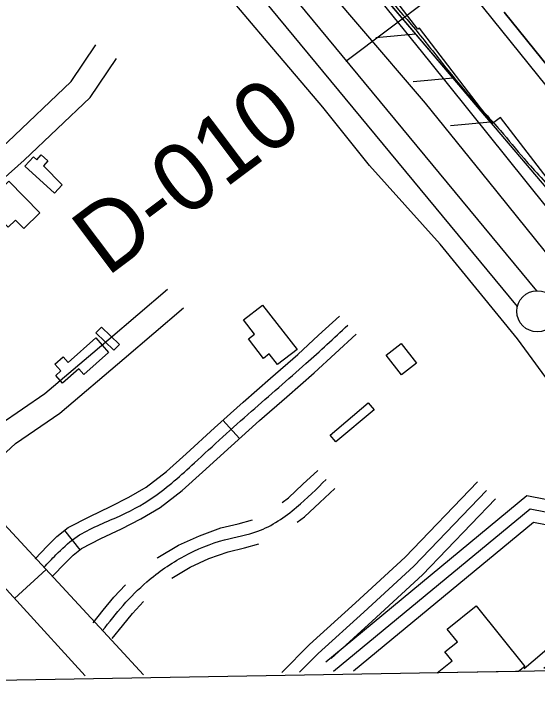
# Model space of a CAD drawing. Extents: x 3887375 to 3925618, y 296674 to 322633.
# Drawn here: x 3900685 to 3901319, y 302226 to 303069 of the extents above; entities that cross this region are included whole.
import ezdxf

# ---------------------------------------------------------------- set-up
doc = ezdxf.new("R2010")
doc.units = 0
for name, color, linetype in [('V-BLDG-OTLN', 7, 'Continuous'), ('V-GRID-FRAM', 7, 'Continuous'), ('V-LEVE-TOET', 7, 'Continuous'), ('V-RIVR-EDGE', 7, 'Continuous'), ('V-RIVR-RANG', 7, 'Continuous'), ('V-RIVR-RANG-IDEN', 7, 'Continuous'), ('V-ROAD-CNTR', 7, 'Continuous'), ('V-RRAP-FSHR', 7, 'Continuous'), ('V-RRAP-RVMT', 7, 'Continuous'), ('V-SURV-LINE', 7, 'Continuous'), ('V-TOPO-DPTH', 7, 'Continuous'), ('V-TOPO-MINR', 7, 'Continuous')]:
    doc.layers.add(name, color=color, linetype=linetype)

msp = doc.modelspace()

# ---------------------------------------------------------------- linework, layer by layer
at = {"layer": 'V-BLDG-OTLN'}
for p, q in [((3901210.31, 302323.14), (3901245.46, 302351.33)), ((3901245.46, 302351.33), (3901304.43, 302277.8)), ((3901222.75, 302307.63), (3901210.31, 302323.14)), ((3901207.46, 302295.38), (3901222.75, 302307.63)), ((3901216.25, 302284.42), (3901207.46, 302295.38)), ((3901198.09, 302269.86), (3901216.25, 302284.42)), ((3901296.64, 302271.55), (3901198.09, 302269.86)), ((3901304.43, 302277.8), (3901296.64, 302271.55))]:
    msp.add_line(p, q, dxfattribs=at)
for points in [[(3900734.3, 302851.99), (3900698.37, 302884.51), (3900708.87, 302896.11), (3900712.89, 302892.47), (3900718.1, 302898.22), (3900726, 302891.07), (3900720.7, 302885.21), (3900743.46, 302862)], [(3900678.71, 302866.36), (3900716.38, 302827.94), (3900696.96, 302808.89), (3900686.85, 302819.2), (3900678.14, 302810.66), (3900656.59, 302832.65), (3900665.03, 302840.92), (3900659.02, 302847.06)], [(3900986.36, 302716), (3901028.21, 302662.4), (3901004.6, 302643.96), (3900994.54, 302656.85), (3900987.64, 302651.45), (3900969.25, 302675), (3900976.78, 302680.88), (3900963.37, 302698.05)], [(3900806.04, 302661.34), (3900784.25, 302682.28), (3900791.02, 302689.33), (3900812.82, 302668.38)], [(3900784.12, 302676.41), (3900799.83, 302658.81), (3900769.83, 302632.04), (3900763.78, 302638.82), (3900744.06, 302621.22), (3900735.65, 302630.65), (3900741.85, 302636.18), (3900734.49, 302644.42), (3900744.69, 302653.52), (3900750.79, 302646.68)], [(3901172.98, 302645.59), (3901154.96, 302631.45), (3901136.27, 302655.27), (3901154.29, 302669.41)], [(3901075.36, 302550.07), (3901068.18, 302558.53), (3901114.29, 302597.64), (3901121.46, 302589.18)]]:
    msp.add_lwpolyline(points, close=True, dxfattribs=at)
at = {"layer": 'V-GRID-FRAM'}
msp.add_lwpolyline([(3891343.33, 320285.84), (3923192.81, 320832.52), (3923512.79, 302652.88), (3891647.44, 302105.93), (3891343.33, 320285.84)], dxfattribs=at)
at = {"layer": 'V-LEVE-TOET'}
for points in [[(3901707.73, 302278.61), (3901647.69, 302352.58), (3901568.61, 302454.8), (3901489.37, 302571.22), (3901419.63, 302666.92), (3901350.94, 302753.56), (3901260.77, 302865.88), (3901184.04, 302961.13), (3901104.11, 303054.27), (3901034.71, 303135.98), (3900953.2, 303236.1), (3900808.82, 303408.54), (3900661.39, 303583.59), (3900535.58, 303736.38), (3900409.95, 303890.67), (3900289.1, 304039.54), (3900169.55, 304191.45), (3900063.81, 304326.29), (3899978.96, 304436.59), (3899860.38, 304585.86), (3899743.53, 304733.26)], [(3901593.34, 302276.64), (3901551.16, 302327.07), (3901473.76, 302430.82), (3901390.76, 302544.92), (3901295.47, 302675.34), (3901201.49, 302790.08), (3901115.87, 302885.42), (3901059.27, 302956.11), (3900993.13, 303034.26), (3900919.31, 303122.17), (3900794.44, 303275.91), (3900678.06, 303414.99), (3900578.17, 303534.01), (3900459.67, 303676.09), (3900342.15, 303815.91), (3900217.23, 303973.44), (3900106.77, 304107.28), (3900018.3, 304237.4), (3899953.62, 304320.11), (3899883.39, 304409.19), (3899779.41, 304538), (3899658.35, 304689.71)]]:
    msp.add_lwpolyline(points, dxfattribs=at)
at = {"layer": 'V-RIVR-EDGE'}
msp.add_spline([(3894498.05, 310522.42), (3894530.03, 310496.11), (3894553.78, 310474.69), (3894579.94, 310451.31), (3894614.83, 310419.17), (3894633.24, 310400.67), (3894662.79, 310372.43), (3894685.08, 310353.44), (3894692.35, 310347.11), (3894709.79, 310328.13), (3894746.59, 310285.3), (3894785.84, 310252.18), (3894809.57, 310225.9), (3894830.41, 310205.45), (3894852.71, 310189.85), (3894866.75, 310171.85), (3894915.18, 310120.25), (3894950.06, 310083.74), (3894971.37, 310062.81), (3894999, 310039.43), (3895025.16, 310017.03), (3895052.79, 309992.68), (3895092.99, 309952.27), (3895110.91, 309932.8), (3895141.44, 309903.1), (3895188.91, 309855.88), (3895222.82, 309821.31), (3895255.75, 309784.32), (3895319.22, 309722.49), (3895350.7, 309688.42), (3895358.44, 309676.26), (3895364.73, 309669.44), (3895374.92, 309663.11), (3895388.97, 309650.44), (3895410.77, 309628.05), (3895448.54, 309583.28), (3895480.52, 309554.06), (3895503.76, 309527.78), (3895533.8, 309499.54), (3895577.4, 309454.75), (3895606.95, 309425.54), (3895653.45, 309378.81), (3895685.92, 309349.1), (3895719.83, 309314.54), (3895749.38, 309285.81), (3895790.55, 309242.49), (3895837.06, 309195.75), (3895863.69, 309164.12), (3895900.02, 309127.61), (3895944.1, 309081.37), (3895955.73, 309070.65), (3895974.63, 309054.58), (3896002.25, 309033.14), (3896032.78, 309003.93), (3896062.81, 308972.29), (3896082.67, 308950.39), (3896119.48, 308911.93), (3896139.34, 308892.46), (3896151.96, 308889.51), (3896163.12, 308883.66), (3896167.95, 308873.93), (3896170.35, 308862.27), (3896184.39, 308844.27), (3896211.03, 308816.04), (3896224.12, 308810.18), (3896236.73, 308802.37), (3896249.8, 308786.8), (3896255.61, 308776.59), (3896270.64, 308766.35), (3896280.32, 308753.22), (3896295.82, 308737.15), (3896375.27, 308661.2), (3896425.17, 308610.08), (3896464.41, 308570.65), (3896519.63, 308515.64), (3896548.69, 308483.03), (3896563.22, 308467.45), (3896597.61, 308430.94), (3896635.89, 308396.37), (3896666.41, 308365.7), (3896681.42, 308349.64), (3896712.43, 308320.42), (3896746.34, 308287.31), (3896777.36, 308260.04), (3896801.58, 308235.7), (3896820.47, 308215.26), (3896842.76, 308195.29), (3896851.46, 308181.19), (3896882.46, 308148.57), (3896918.81, 308116.43), (3896962.9, 308074.56), (3896997.76, 308033.19), (3897029.24, 307998.63), (3897042.32, 307985), (3897083.5, 307945.57), (3897107.23, 307918.31), (3897123.21, 307898.85), (3897130, 307898.83), (3897142.13, 307892.97), (3897145.99, 307882.28), (3897149.85, 307874.01), (3897162.93, 307860.38), (3897188.6, 307833.12), (3897229.29, 307788.83), (3897267.56, 307752.31), (3897300.5, 307715.81), (3897334.4, 307680.27), (3897361.53, 307651.07), (3897384.78, 307628.19), (3897411.42, 307598.98), (3897445.81, 307563.45), (3897494.26, 307516.71), (3897543.17, 307462.68), (3897584.83, 307418.38), (3897609.05, 307394.04), (3897646.83, 307355.58), (3897678.81, 307323.94), (3897715.15, 307290.34), (3897751.96, 307253.34), (3897766.97, 307236.31), (3897837.68, 307158.43), (3897886.6, 307104.4), (3897936, 307048.43), (3897965.54, 307015.34), (3898010.59, 306970.06), (3898027.54, 306949.14), (3898044.99, 306935.98), (3898063.87, 306914.08), (3898089.05, 306882.46), (3898117.14, 306854.7), (3898160.23, 306801.18), (3898195.59, 306763.7), (3898235.79, 306719.89), (3898261.46, 306693.6), (3898297.3, 306650.78), (3898332.65, 306612.33), (3898369.94, 306568.04), (3898397.54, 306534.95), (3898422.23, 306505.75), (3898462.9, 306455.14), (3898495.34, 306417.18), (3898521.97, 306382.15), (3898601.37, 306284.34), (3898652.22, 306228.37), (3898693.37, 306177.28), (3898729.68, 306130.57), (3898777.13, 306074.12), (3898825.55, 306014.26), (3898848.79, 305986.04), (3898903.98, 305917.43), (3898957.25, 305854.65), (3898984.35, 305818.16), (3899049.73, 305744.67), (3899107.84, 305679.45), (3899129.14, 305651.72), (3899142.69, 305630.31), (3899156.24, 305611.83), (3899175.12, 305587.98), (3899224.03, 305529.59), (3899255.99, 305493.57), (3899288.9, 305449.3), (3899312.61, 305415.24), (3899375.55, 305336.9), (3899410.9, 305296.02), (3899442.85, 305252.24), (3899470.43, 305211.86), (3899531.42, 305133.52), (3899579.35, 305071.24), (3899616.14, 305025.99), (3899647.13, 304986.09), (3899690.7, 304931.1), (3899729.41, 304876.62), (3899753.62, 304846.93), (3899770.56, 304821.64), (3899817.5, 304755.48), (3899845.56, 304713.16), (3899868.3, 304677.16), (3899889.6, 304650.4), (3899911.39, 304623.64), (3899955.44, 304569.14), (3899987.39, 304526.81), (3900012.56, 304494.21), (3900025.63, 304476.21), (3900037.24, 304456.75), (3900061.94, 304431.93), (3900070.67, 304424.13), (3900074.53, 304414.41), (3900074.99, 304404.21), (3900073.03, 304397.9), (3900071.55, 304388.68), (3900071.54, 304383.82), (3900075.9, 304378.96), (3900087.05, 304374.07), (3900096.26, 304367.74), (3900108.39, 304362.37), (3900117.11, 304353.6), (3900140.84, 304326.35), (3900165.54, 304299.09), (3900226.07, 304227.55), (3900277.87, 304164.29), (3900319.98, 304105.91), (3900352.41, 304062.61), (3900384.36, 304023.2), (3900411.47, 303988.16), (3900438.1, 303954.1), (3900462.8, 303926.85), (3900556.24, 303812.49), (3900597.89, 303762.85), (3900633.71, 303716.63), (3900652.59, 303691.33), (3900701.96, 303626.62), (3900774.57, 303530.77), (3900849.12, 303437.34), (3900903.35, 303371.16), (3900928.05, 303343.42), (3900948.87, 303317.63), (3901001.17, 303258.26), (3901038.95, 303216.88), (3901074.78, 303173.09), (3901092.2, 303147.31), (3901171.6, 303050.47), (3901205, 303008.62), (3901238.41, 302968.23), (3901274.74, 302927.83), (3901303.3, 302893.77), (3901343.98, 302847.53), (3901366.73, 302816.4), (3901404.5, 302770.17), (3901454.38, 302715.17), (3901507.18, 302659.19), (3901551.73, 302608.09), (3901584.66, 302570.61), (3901650.02, 302491.29), (3901680.99, 302443.62), (3901717.76, 302388.17), (3901785.52, 302298.16), (3901789.55, 302293.3)], degree=3, dxfattribs=at)
at = {"layer": 'V-RIVR-RANG'}
msp.add_line((3901087.36, 303011.91), (3901550.12, 303361.55), dxfattribs=at)
at = {"layer": 'V-ROAD-CNTR'}
for p, q in [((3900938.43, 302576.42), (3900958.54, 302554.16)), ((3900746.3, 302442.68), (3900764.77, 302419.05))]:
    msp.add_line(p, q, dxfattribs=at)
for points in [[(3899638.53, 303569.43), (3900171.85, 302992.43), (3900808.57, 302303.86), (3900841.95, 302267.5)], [(3899598.23, 303541.09), (3900011.3, 303094.74), (3900456.04, 302612.5), (3900771.37, 302266.29)], [(3900454.6, 302686.66), (3900478.65, 302727.49), (3900535.6, 302787.76), (3900677.14, 302913.94), (3900754.25, 302987.27), (3900784.37, 303031.91)], [(3900475.87, 302663.65), (3900502.78, 302709.35), (3900556.53, 302766.22), (3900697.47, 302891.87), (3900777.29, 302967.78), (3900809.24, 303015.12)], [(3900609.76, 302518.86), (3900638.62, 302544.46), (3900668.31, 302571.77), (3900722.43, 302608.93), (3900799.2, 302674), (3900871.24, 302735.64)], [(3900630.13, 302496.83), (3900658.73, 302522.2), (3900687.05, 302548.25), (3900740.67, 302585.06), (3900818.65, 302651.16), (3900890.74, 302712.85)], [(3900710.69, 302408.39), (3900725.28, 302423.6), (3900736.86, 302435.3), (3900750.81, 302446.21), (3900776.92, 302459.76), (3900801.98, 302471.69), (3900824.34, 302483.13), (3900845.39, 302495.43), (3900869.88, 302514.45), (3900893.65, 302535.72), (3900928.11, 302567.1), (3900962.85, 302598.48), (3900996.16, 302627.35), (3901028.99, 302656.32), (3901054.18, 302679.48), (3901079.49, 302702.74)], [(3900732.34, 302387.62), (3900746.77, 302402.66), (3900756.84, 302412.84), (3900767.09, 302420.86), (3900790.28, 302432.89), (3900815.26, 302444.79), (3900838.75, 302456.81), (3900862.23, 302470.52), (3900889.1, 302491.4), (3900913.75, 302513.45), (3900948.27, 302544.88), (3900982.73, 302576.01), (3901015.91, 302604.77), (3901049.06, 302634.03), (3901074.49, 302657.39), (3901099.79, 302680.66)], [(3901010.27, 302476.61), (3901017.78, 302482.31), (3901035.26, 302498.69), (3901053.32, 302515.61)], [(3901009.78, 302270.38), (3901043.45, 302304.33), (3901098.94, 302354.85), (3901159.35, 302410.24), (3901246.84, 302501.73)], [(3901028.39, 302452.7), (3901037.15, 302459.35), (3901055.78, 302476.8), (3901073.83, 302493.73)], [(3901031.27, 302270.75), (3901053.84, 302293.5), (3901109.06, 302343.78), (3901169.85, 302399.51), (3901257.68, 302491.36)], [(3901350.86, 302276.23), (3901439.92, 302351.9), (3901441.44, 302409.91), (3901393.16, 302467.75), (3901306.69, 302484.63), (3901062.99, 302283.01)], [(3901069.47, 302287.45), (3901119.17, 302332.7), (3901180.35, 302388.79), (3901268.52, 302480.99)], [(3901327.22, 302275.83), (3901425.1, 302358.99), (3901426.3, 302404.64), (3901385.06, 302454.05), (3901310.79, 302468.54), (3901072.55, 302271.46)], [(3900858.55, 302409.11), (3900859.41, 302409.78), (3900884.54, 302424.96), (3900910.01, 302436.35), (3900936, 302445.72), (3900956.78, 302450.84), (3900974.14, 302455.58)], [(3901303.58, 302275.42), (3901410.28, 302366.08), (3901411.16, 302399.37), (3901376.96, 302440.35), (3901314.88, 302452.46), (3901096.58, 302271.87)], [(3900876.47, 302385.04), (3900898.48, 302398.32), (3900921.24, 302408.51), (3900944.7, 302416.96), (3900964.32, 302421.8), (3900982.04, 302426.64)], [(3900724.01, 302395.31), (3900685.81, 302360.23)], [(3900780.88, 302330.7), (3900793.32, 302345.98), (3900806.07, 302361.64), (3900820.2, 302376.86)], [(3900804.14, 302311.76), (3900816.58, 302327.04), (3900828.71, 302341.94), (3900842.19, 302356.45)]]:
    msp.add_lwpolyline(points, dxfattribs=at)
for points in [[(3900721.52, 302398.01), (3900736.02, 302413.13), (3900758.95, 302433.54), (3900808.62, 302458.24), (3900853.81, 302482.98), (3900903.7, 302524.58), (3900972.79, 302587.25), (3901039.03, 302645.17), (3901089.64, 302691.7)], [(3900792.51, 302321.23), (3900817.39, 302351.79), (3900846.3, 302380.42), (3900891.51, 302411.64), (3900940.35, 302431.34), (3900980.66, 302441.81), (3901027.47, 302470.83), (3901063.58, 302504.67)]]:
    msp.add_spline(points, degree=3, dxfattribs=at)
at = {"layer": 'V-RRAP-FSHR'}
for p, q in [((3901172.29, 303044.93), (3901123.66, 303040.42)), ((3901217.56, 302991.55), (3901168.94, 302987.04)), ((3901262.84, 302938.16), (3901214.22, 302933.65))]:
    msp.add_line(p, q, dxfattribs=at)
for points in [[(3891468.38, 312810.08), (3891592.07, 312735.45), (3892299.93, 312230.23), (3893039.21, 311719.28), (3893631.65, 311277.12), (3894117.75, 310846), (3894636.93, 310371.58), (3895241.96, 309786.83), (3895348.82, 309658.26), (3895604.32, 309398.25), (3896430.18, 308555.06), (3897023.94, 307973.73), (3897641.56, 307335.08), (3898033.61, 306930.91), (3898562.18, 306317.87), (3899280.35, 305434.23), (3899629.7, 304981.52), (3900046.19, 304414.8), (3900422.65, 303959.37), (3901188.76, 303011.8), (3901775.81, 302279.78)], [(3901789.31, 302283.76), (3901580.61, 302550.11), (3901486.3, 302669.72), (3901336.95, 302850.78), (3900933.83, 303326.1), (3900183.19, 304271.3)], [(3901172.29, 303044.93), (3901127.01, 303098.32)], [(3901217.56, 302991.55), (3901172.29, 303044.93)], [(3901262.84, 302938.16), (3901217.56, 302991.55)]]:
    msp.add_lwpolyline(points, dxfattribs=at)
at = {"layer": 'V-RRAP-RVMT'}
for p, q in [((3901174.77, 303050.75), (3901085.03, 303167.85)), ((3901176.47, 303052.04), (3901174.77, 303050.75)), ((3901265.08, 302936.46), (3901176.47, 303052.04)), ((3901274.65, 302943.79), (3901265.08, 302936.46)), ((3901362.38, 302829.36), (3901274.65, 302943.79))]:
    msp.add_line(p, q, dxfattribs=at)
at = {"layer": 'V-SURV-LINE'}
for points in [[(3900476.9, 303751.75), (3901318.35, 302733.54)], [(3901295.22, 302714.43), (3900453.77, 303732.64)]]:
    msp.add_lwpolyline(points, dxfattribs=at)
msp.add_circle((3901319.51, 302708.59), 25, dxfattribs=at)
at = {"layer": 'V-TOPO-DPTH'}
msp.add_lwpolyline([(3901947.42, 302282.72), (3901937.57, 302294.74), (3901873.92, 302369.37), (3901854.47, 302391.78), (3901834.78, 302413.96), (3901814.71, 302435.82), (3901794.4, 302457.44), (3901774.11, 302479.09), (3901754.11, 302500.99), (3901734.52, 302523.27), (3901715.22, 302545.8), (3901465.13, 302843.37), (3901439.94, 302873.53), (3901414.87, 302903.79), (3901389.98, 302934.2), (3901365.22, 302964.71), (3901360.45, 302970.63), (3901333.41, 303004.18), (3901306.37, 303037.74), (3901279.36, 303071.32)], dxfattribs=at)
at = {"layer": 'V-TOPO-MINR'}
for points in [[(3900982.23, 303414.35), (3901363.36, 302940.95), (3901369.68, 302933.1), (3901376, 302925.26), (3901382.32, 302917.42), (3901388.65, 302909.58), (3901395, 302901.76), (3901401.35, 302893.94), (3901407.74, 302886.15), (3901414.13, 302878.37), (3901810.74, 302397.51), (3901821.85, 302384.24), (3901833.1, 302371.09), (3901844.55, 302358.11), (3901856.14, 302345.25), (3901867.76, 302332.42), (3901879.29, 302319.5), (3901890.68, 302306.47), (3901901.98, 302293.36), (3901911.58, 302282.11)], [(3901279.36, 303071.32), (3901306.37, 303037.74), (3901333.41, 303004.18), (3901360.45, 302970.63), (3901365.22, 302964.71), (3901389.98, 302934.2), (3901414.87, 302903.79), (3901439.94, 302873.53), (3901465.13, 302843.37), (3901715.22, 302545.8), (3901734.52, 302523.27), (3901754.11, 302500.99), (3901774.11, 302479.09), (3901794.4, 302457.44), (3901814.71, 302435.82), (3901834.78, 302413.96), (3901854.47, 302391.78), (3901873.92, 302369.37), (3901937.57, 302294.74), (3901947.42, 302282.72)]]:
    msp.add_lwpolyline(points, dxfattribs=at)

# ---------------------------------------------------------------- texts
at = {"layer": 'V-RIVR-RANG-IDEN'}
msp.add_text('D-010', height=83, rotation=36.93233, dxfattribs=at).set_placement((3900797.83, 302749.64))

doc.saveas('drawing.dxf')
